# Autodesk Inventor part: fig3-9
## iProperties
Created: 2005-02
Part Number: fig3-9
Document SubType Name: Modeling
Designer: CADCIM
Manufacturer: Standard
Standards Organization: Custom
Author: CADCIM
